Omron CX-Programmer project 新規ﾌﾟﾛｼﾞｪｸﾄ (CX-Programmer 9.70)

# PLC エレベータPLC: CJ2M CPU34
I/O table (CPU CJ2M-CPU34): rack 0 slot 0 CJ1W-ID231; rack 0 slot 1 CJ1W-ID231; rack 0 slot 2 CJ1W-OD231; rack 0 slot 11 CJ2M-EIP21

## Global symbols (name address type ; comment)
0.00 BOOL  ; 1F行PB(かご内)
0.01 BOOL  ; 2F行PB(かご内)
0.02 BOOL  ; 3F行PB(かご内)
0.03 BOOL  ; 開PB(かご内)
0.04 BOOL  ; 閉PB(かご内)
0.05 BOOL  ; 扉開LS(かご内)
0.06 BOOL  ; 扉閉LS(かご内)
1.00 BOOL  ; 呼びPB(1F)
1.01 BOOL  ; 呼びPB(2F)
1.02 BOOL  ; 呼びPB(3F)
1.03 BOOL  ; かご上限LS
1.04 BOOL  ; かご下限LS
1.05 BOOL  ; かご到着LS(1F)
1.06 BOOL  ; かご到着LS(2F)
1.07 BOOL  ; かご到着LS(3F)
1.08 BOOL  ; 扉開LS(1F)
1.09 BOOL  ; 扉閉LS(1F)
1.10 BOOL  ; 扉開LS(2F)
1.11 BOOL  ; 扉閉LS(2F)
1.12 BOOL  ; 扉開LS(3F)
1.13 BOOL  ; 扉閉LS(3F)
2.00 BOOL  ; 運転
2.01 BOOL  ; 調整
2.02 BOOL  ; 上昇PB
2.03 BOOL  ; 下降PB
2.04 BOOL  ; かご扉開PB
2.05 BOOL  ; かご扉閉PB
2.06 BOOL  ; 1F扉開PB
2.07 BOOL  ; 1F扉閉PB
2.08 BOOL  ; 2F扉開PB
2.09 BOOL  ; 2F扉閉PB
2.10 BOOL  ; 3F扉開PB
2.11 BOOL  ; 3F扉閉PB
4.00 BOOL  ; 下降
4.01 BOOL  ; 上昇
4.02 BOOL  ; 昇降ﾌﾞﾚｰｷ
4.03 BOOL  ; 扉開(かご)
4.04 BOOL  ; 扉閉(かご)
4.05 BOOL  ; 扉開(1F)
4.06 BOOL  ; 扉閉(1F)
4.07 BOOL  ; 扉開(2F)
4.08 BOOL  ; 扉閉(2F)
4.09 BOOL  ; 扉開(3F)
4.10 BOOL  ; 扉閉(3F)
5.00 BOOL  ; 行先1F表示(かご)
5.01 BOOL  ; 行先2F表示(かご)
5.02 BOOL  ; 行先3F表示(かご)
5.03 BOOL  ; 1F呼び表示
5.04 BOOL  ; 2F呼び表示
5.05 BOOL  ; 3F呼び表示
5.15 BOOL  ; 運転ﾓｰﾄﾞ
T0000 BOOL  ; 扉開遅延
T0001 BOOL  ; 扉閉待機
T0002 BOOL  ; 扉閉後動作完了信号遅延
W0.00 BOOL  ; 1F行き(かご内)
W0.01 BOOL  ; 2F行き(かご内)
W0.02 BOOL  ; 3F行き(かご内)
W0.03 BOOL  ; 下降信号
W0.04 BOOL  ; 上昇信号
W0.05 BOOL  ; 移動なし
W0.08 BOOL  ; 扉開(かご)
W0.09 BOOL  ; 扉閉(かご)
W10.00 BOOL  ; 停止中
W10.01 BOOL  ; 昇降開始
W10.02 BOOL  ; 下降
W10.03 BOOL  ; 上昇
W10.04 BOOL  ; 昇降停止
W10.05 BOOL  ; 1F呼び
W10.06 BOOL  ; 2F呼び
W10.07 BOOL  ; 3F呼び
W10.08 BOOL  ; 下降信号
W10.09 BOOL  ; 上昇信号
W10.10 BOOL  ; 1F呼び
W10.11 BOOL  ; 2F呼び
W10.12 BOOL  ; 3F呼び
W11.00 BOOL  ; 階到着扉開遅延
W11.02 BOOL  ; 扉閉待機
W11.03 BOOL  ; 扉閉完了
W11.06 BOOL  ; 扉開'(各階)
W11.07 BOOL  ; 扉閉(各階)

## Program 新規ﾌﾟﾛｸﾞﾗﾑ1 (cyclic task 0)

### Section かご内

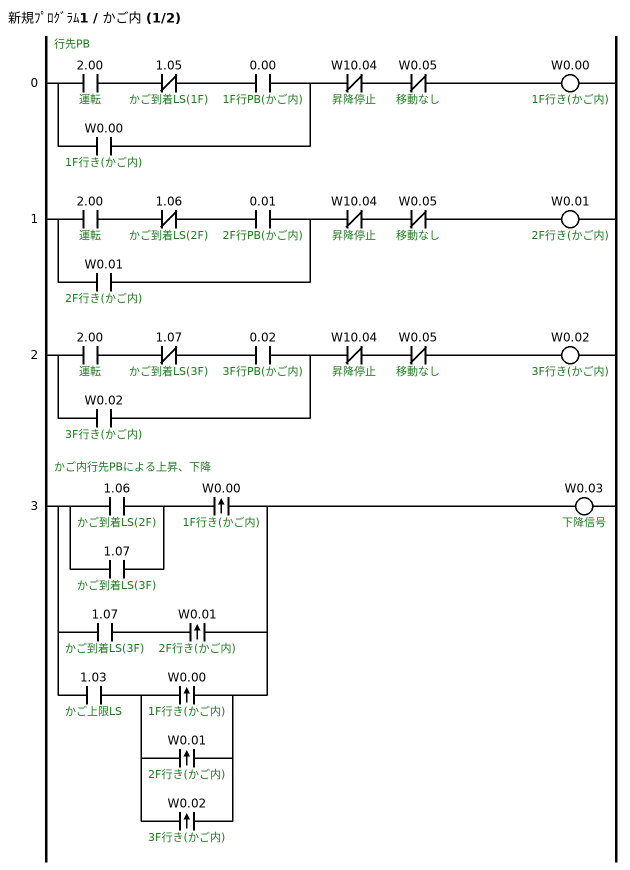
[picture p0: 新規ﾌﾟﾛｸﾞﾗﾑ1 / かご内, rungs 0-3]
; rung 0: 行先PB
LD 2.00  ; 運転
ANDNOT 1.05  ; かご到着LS(1F)
AND 0.00  ; 1F行PB(かご内)
OR W0.00  ; 1F行き(かご内)
ANDNOT W10.04  ; 昇降停止
ANDNOT W0.05  ; 移動なし
OUT W0.00  ; 1F行き(かご内)
; rung 1
LD 2.00  ; 運転
ANDNOT 1.06  ; かご到着LS(2F)
AND 0.01  ; 2F行PB(かご内)
OR W0.01  ; 2F行き(かご内)
ANDNOT W10.04  ; 昇降停止
ANDNOT W0.05  ; 移動なし
OUT W0.01  ; 2F行き(かご内)
; rung 2
LD 2.00  ; 運転
ANDNOT 1.07  ; かご到着LS(3F)
AND 0.02  ; 3F行PB(かご内)
OR W0.02  ; 3F行き(かご内)
ANDNOT W10.04  ; 昇降停止
ANDNOT W0.05  ; 移動なし
OUT W0.02  ; 3F行き(かご内)
; rung 3: かご内行先PBによる上昇、下降
LD 1.06  ; かご到着LS(2F)
OR 1.07  ; かご到着LS(3F)
@AND W0.00  ; 1F行き(かご内)
LD 1.07  ; かご到着LS(3F)
@AND W0.01  ; 2F行き(かご内)
ORLD
LD 1.03  ; かご上限LS
@LD W0.00  ; 1F行き(かご内)
@OR W0.01  ; 2F行き(かご内)
@OR W0.02  ; 3F行き(かご内)
ANDLD
ORLD
OUT W0.03  ; 下降信号

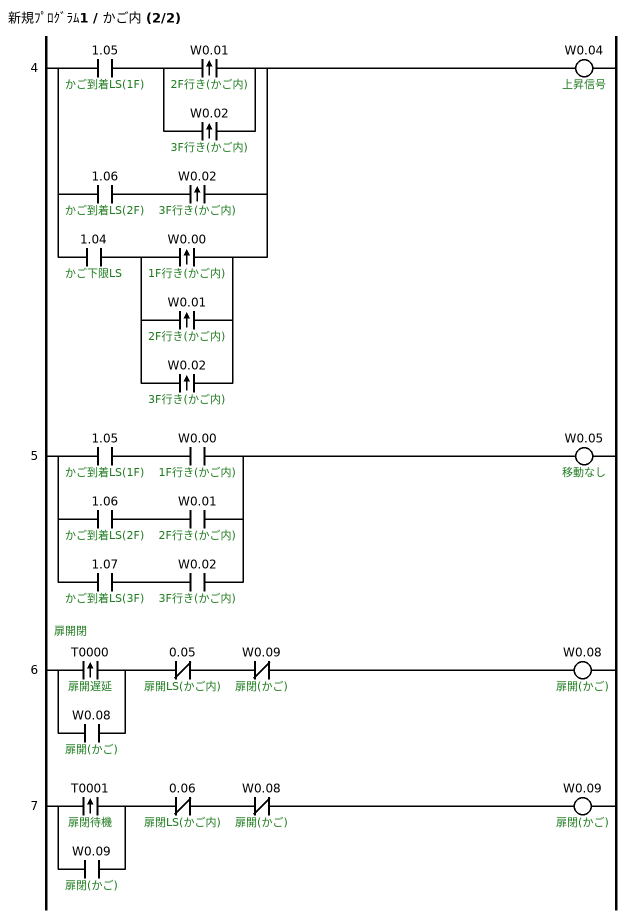
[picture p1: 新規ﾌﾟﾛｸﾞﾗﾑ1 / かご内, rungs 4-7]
; rung 4
LD 1.05  ; かご到着LS(1F)
@LD W0.01  ; 2F行き(かご内)
@OR W0.02  ; 3F行き(かご内)
ANDLD
LD 1.06  ; かご到着LS(2F)
@AND W0.02  ; 3F行き(かご内)
ORLD
LD 1.04  ; かご下限LS
@LD W0.00  ; 1F行き(かご内)
@OR W0.01  ; 2F行き(かご内)
@OR W0.02  ; 3F行き(かご内)
ANDLD
ORLD
OUT W0.04  ; 上昇信号
; rung 5
LD 1.05  ; かご到着LS(1F)
AND W0.00  ; 1F行き(かご内)
LD 1.06  ; かご到着LS(2F)
AND W0.01  ; 2F行き(かご内)
ORLD
LD 1.07  ; かご到着LS(3F)
AND W0.02  ; 3F行き(かご内)
ORLD
OUT W0.05  ; 移動なし
; rung 6: 扉開閉
@LD T0000  ; 扉開遅延
OR W0.08  ; 扉開(かご)
ANDNOT 0.05  ; 扉開LS(かご内)
ANDNOT W0.09  ; 扉閉(かご)
OUT W0.08  ; 扉開(かご)
; rung 7
@LD T0001  ; 扉閉待機
OR W0.09  ; 扉閉(かご)
ANDNOT 0.06  ; 扉閉LS(かご内)
ANDNOT W0.08  ; 扉開(かご)
OUT W0.09  ; 扉閉(かご)

### Section 地上

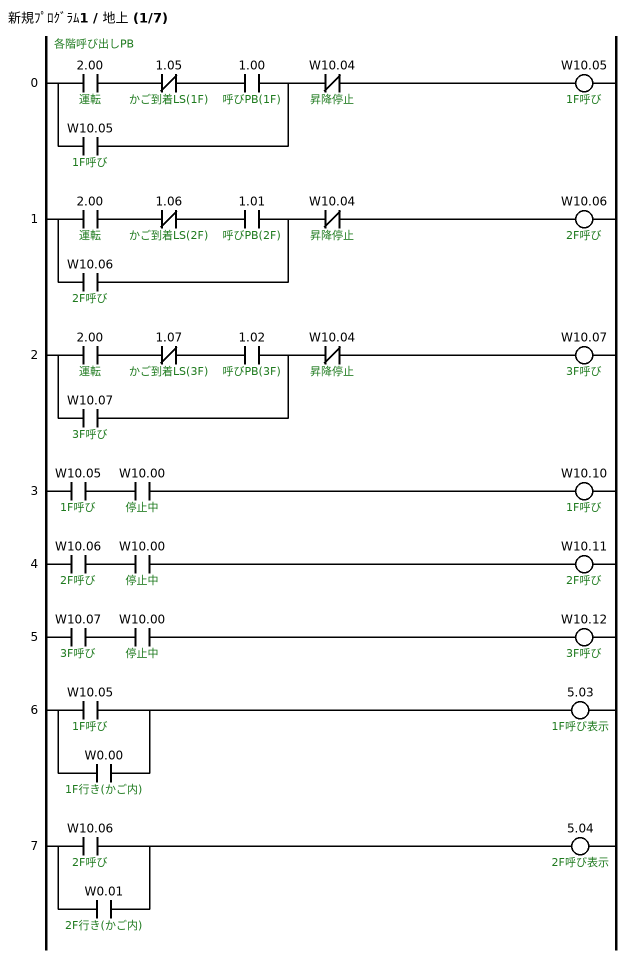
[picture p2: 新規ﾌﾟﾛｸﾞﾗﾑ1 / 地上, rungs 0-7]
; rung 0: 各階呼び出しPB
LD 2.00  ; 運転
ANDNOT 1.05  ; かご到着LS(1F)
AND 1.00  ; 呼びPB(1F)
OR W10.05  ; 1F呼び
ANDNOT W10.04  ; 昇降停止
OUT W10.05  ; 1F呼び
; rung 1
LD 2.00  ; 運転
ANDNOT 1.06  ; かご到着LS(2F)
AND 1.01  ; 呼びPB(2F)
OR W10.06  ; 2F呼び
ANDNOT W10.04  ; 昇降停止
OUT W10.06  ; 2F呼び
; rung 2
LD 2.00  ; 運転
ANDNOT 1.07  ; かご到着LS(3F)
AND 1.02  ; 呼びPB(3F)
OR W10.07  ; 3F呼び
ANDNOT W10.04  ; 昇降停止
OUT W10.07  ; 3F呼び
; rung 3
LD W10.05  ; 1F呼び
AND W10.00  ; 停止中
OUT W10.10  ; 1F呼び
; rung 4
LD W10.06  ; 2F呼び
AND W10.00  ; 停止中
OUT W10.11  ; 2F呼び
; rung 5
LD W10.07  ; 3F呼び
AND W10.00  ; 停止中
OUT W10.12  ; 3F呼び
; rung 6
LD W10.05  ; 1F呼び
OR W0.00  ; 1F行き(かご内)
OUT 5.03  ; 1F呼び表示
; rung 7
LD W10.06  ; 2F呼び
OR W0.01  ; 2F行き(かご内)
OUT 5.04  ; 2F呼び表示

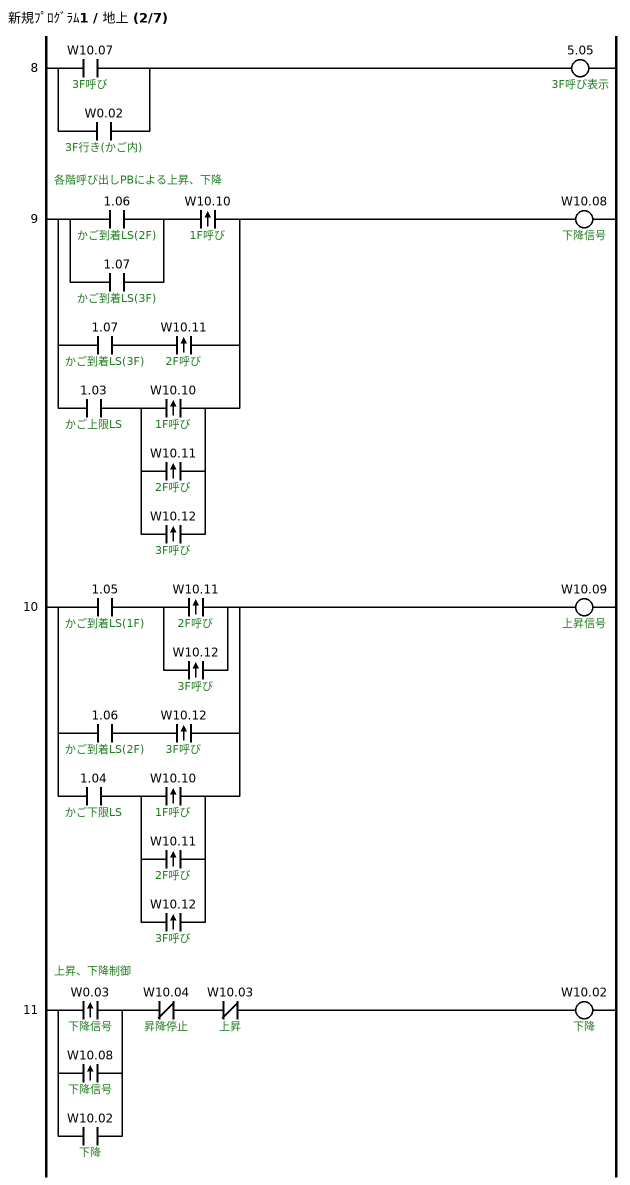
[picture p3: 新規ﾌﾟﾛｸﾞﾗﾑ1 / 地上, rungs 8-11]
; rung 8
LD W10.07  ; 3F呼び
OR W0.02  ; 3F行き(かご内)
OUT 5.05  ; 3F呼び表示
; rung 9: 各階呼び出しPBによる上昇、下降
LD 1.06  ; かご到着LS(2F)
OR 1.07  ; かご到着LS(3F)
@AND W10.10  ; 1F呼び
LD 1.07  ; かご到着LS(3F)
@AND W10.11  ; 2F呼び
ORLD
LD 1.03  ; かご上限LS
@LD W10.10  ; 1F呼び
@OR W10.11  ; 2F呼び
@OR W10.12  ; 3F呼び
ANDLD
ORLD
OUT W10.08  ; 下降信号
; rung 10
LD 1.05  ; かご到着LS(1F)
@LD W10.11  ; 2F呼び
@OR W10.12  ; 3F呼び
ANDLD
LD 1.06  ; かご到着LS(2F)
@AND W10.12  ; 3F呼び
ORLD
LD 1.04  ; かご下限LS
@LD W10.10  ; 1F呼び
@OR W10.11  ; 2F呼び
@OR W10.12  ; 3F呼び
ANDLD
ORLD
OUT W10.09  ; 上昇信号
; rung 11: 上昇、下降制御
@LD W0.03  ; 下降信号
@OR W10.08  ; 下降信号
OR W10.02  ; 下降
ANDNOT W10.04  ; 昇降停止
ANDNOT W10.03  ; 上昇
OUT W10.02  ; 下降

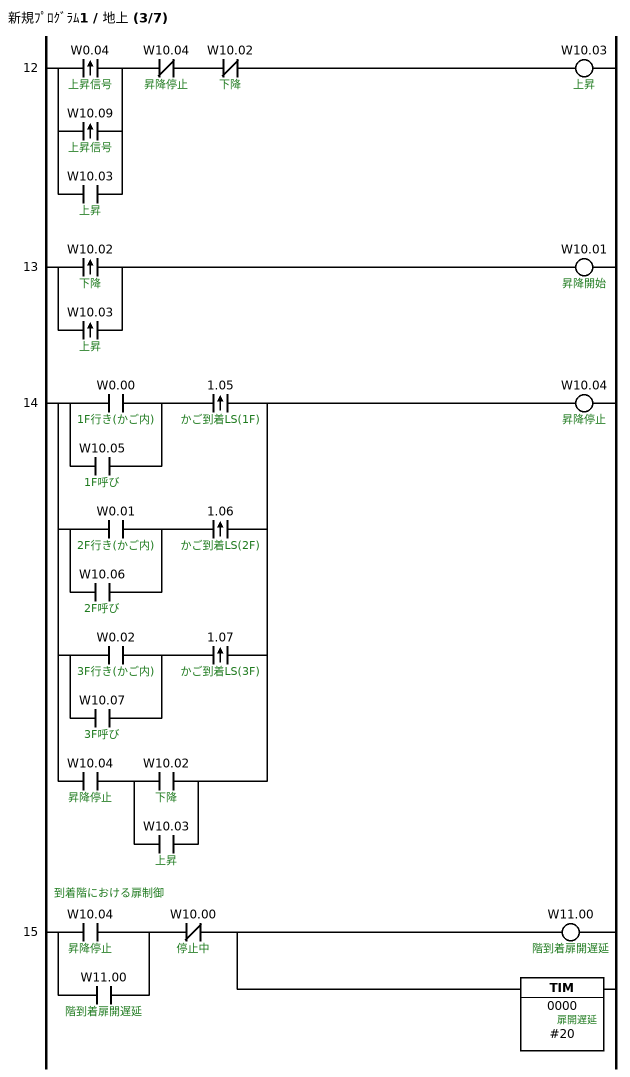
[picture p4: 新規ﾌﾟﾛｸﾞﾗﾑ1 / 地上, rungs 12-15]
; rung 12
@LD W0.04  ; 上昇信号
@OR W10.09  ; 上昇信号
OR W10.03  ; 上昇
ANDNOT W10.04  ; 昇降停止
ANDNOT W10.02  ; 下降
OUT W10.03  ; 上昇
; rung 13
@LD W10.02  ; 下降
@OR W10.03  ; 上昇
OUT W10.01  ; 昇降開始
; rung 14
LD W0.00  ; 1F行き(かご内)
OR W10.05  ; 1F呼び
@AND 1.05  ; かご到着LS(1F)
LD W0.01  ; 2F行き(かご内)
OR W10.06  ; 2F呼び
@AND 1.06  ; かご到着LS(2F)
ORLD
LD W0.02  ; 3F行き(かご内)
OR W10.07  ; 3F呼び
@AND 1.07  ; かご到着LS(3F)
ORLD
LD W10.04  ; 昇降停止
LD W10.02  ; 下降
OR W10.03  ; 上昇
ANDLD
ORLD
OUT W10.04  ; 昇降停止
; rung 15: 到着階における扉制御
LD W10.04  ; 昇降停止
OR W11.00  ; 階到着扉開遅延
ANDNOT W10.00  ; 停止中
OUT W11.00  ; 階到着扉開遅延
TIM 0000 #20  ; 扉開遅延

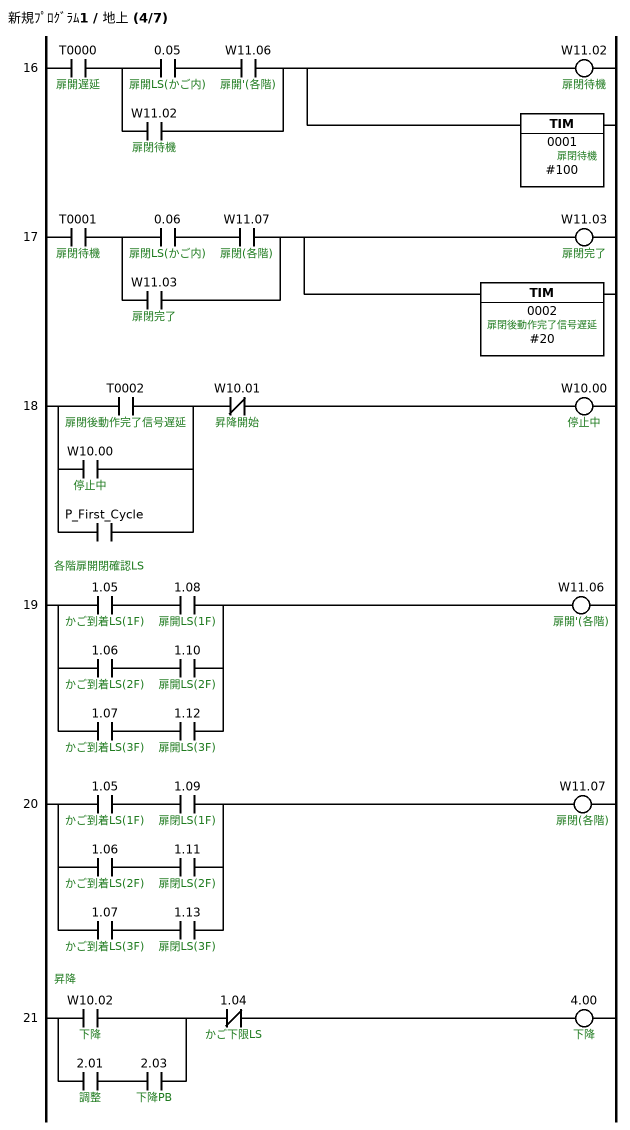
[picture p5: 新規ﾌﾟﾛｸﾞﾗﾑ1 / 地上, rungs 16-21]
; rung 16
LD T0000  ; 扉開遅延
LD 0.05  ; 扉開LS(かご内)
AND W11.06  ; 扉開'(各階)
OR W11.02  ; 扉閉待機
ANDLD
OUT W11.02  ; 扉閉待機
TIM 0001 #100  ; 扉閉待機
; rung 17
LD T0001  ; 扉閉待機
LD 0.06  ; 扉閉LS(かご内)
AND W11.07  ; 扉閉(各階)
OR W11.03  ; 扉閉完了
ANDLD
OUT W11.03  ; 扉閉完了
TIM 0002 #20  ; 扉閉後動作完了信号遅延
; rung 18
LD T0002  ; 扉閉後動作完了信号遅延
OR W10.00  ; 停止中
OR P_First_Cycle
ANDNOT W10.01  ; 昇降開始
OUT W10.00  ; 停止中
; rung 19: 各階扉開閉確認LS
LD 1.05  ; かご到着LS(1F)
AND 1.08  ; 扉開LS(1F)
LD 1.06  ; かご到着LS(2F)
AND 1.10  ; 扉開LS(2F)
ORLD
LD 1.07  ; かご到着LS(3F)
AND 1.12  ; 扉開LS(3F)
ORLD
OUT W11.06  ; 扉開'(各階)
; rung 20
LD 1.05  ; かご到着LS(1F)
AND 1.09  ; 扉閉LS(1F)
LD 1.06  ; かご到着LS(2F)
AND 1.11  ; 扉閉LS(2F)
ORLD
LD 1.07  ; かご到着LS(3F)
AND 1.13  ; 扉閉LS(3F)
ORLD
OUT W11.07  ; 扉閉(各階)
; rung 21: 昇降
LD W10.02  ; 下降
LD 2.01  ; 調整
AND 2.03  ; 下降PB
ORLD
ANDNOT 1.04  ; かご下限LS
OUT 4.00  ; 下降

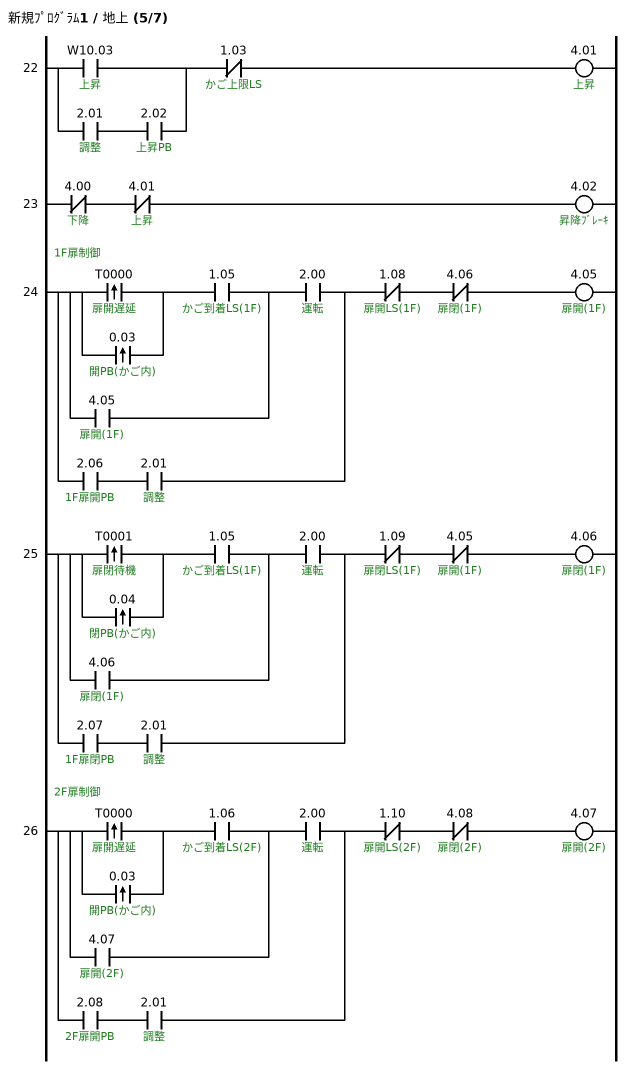
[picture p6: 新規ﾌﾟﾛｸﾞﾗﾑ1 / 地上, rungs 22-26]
; rung 22
LD W10.03  ; 上昇
LD 2.01  ; 調整
AND 2.02  ; 上昇PB
ORLD
ANDNOT 1.03  ; かご上限LS
OUT 4.01  ; 上昇
; rung 23
LDNOT 4.00  ; 下降
ANDNOT 4.01  ; 上昇
OUT 4.02  ; 昇降ﾌﾞﾚｰｷ
; rung 24: 1F扉制御
@LD T0000  ; 扉開遅延
@OR 0.03  ; 開PB(かご内)
AND 1.05  ; かご到着LS(1F)
OR 4.05  ; 扉開(1F)
AND 2.00  ; 運転
LD 2.06  ; 1F扉開PB
AND 2.01  ; 調整
ORLD
ANDNOT 1.08  ; 扉開LS(1F)
ANDNOT 4.06  ; 扉閉(1F)
OUT 4.05  ; 扉開(1F)
; rung 25
@LD T0001  ; 扉閉待機
@OR 0.04  ; 閉PB(かご内)
AND 1.05  ; かご到着LS(1F)
OR 4.06  ; 扉閉(1F)
AND 2.00  ; 運転
LD 2.07  ; 1F扉閉PB
AND 2.01  ; 調整
ORLD
ANDNOT 1.09  ; 扉閉LS(1F)
ANDNOT 4.05  ; 扉開(1F)
OUT 4.06  ; 扉閉(1F)
; rung 26: 2F扉制御
@LD T0000  ; 扉開遅延
@OR 0.03  ; 開PB(かご内)
AND 1.06  ; かご到着LS(2F)
OR 4.07  ; 扉開(2F)
AND 2.00  ; 運転
LD 2.08  ; 2F扉開PB
AND 2.01  ; 調整
ORLD
ANDNOT 1.10  ; 扉開LS(2F)
ANDNOT 4.08  ; 扉閉(2F)
OUT 4.07  ; 扉開(2F)

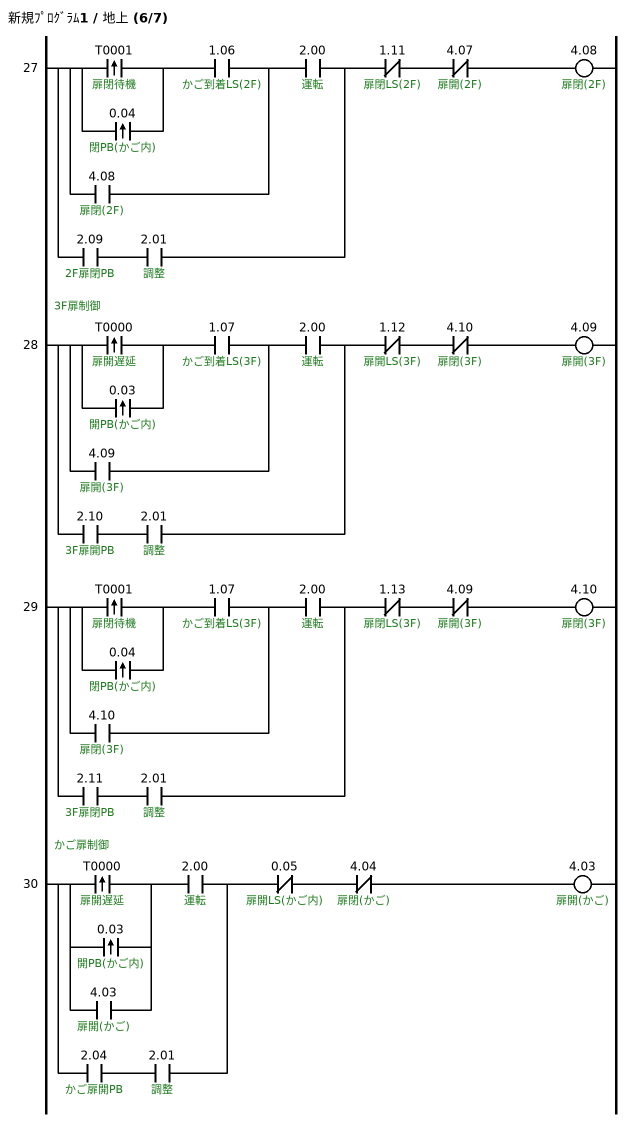
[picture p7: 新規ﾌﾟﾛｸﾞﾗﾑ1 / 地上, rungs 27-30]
; rung 27
@LD T0001  ; 扉閉待機
@OR 0.04  ; 閉PB(かご内)
AND 1.06  ; かご到着LS(2F)
OR 4.08  ; 扉閉(2F)
AND 2.00  ; 運転
LD 2.09  ; 2F扉閉PB
AND 2.01  ; 調整
ORLD
ANDNOT 1.11  ; 扉閉LS(2F)
ANDNOT 4.07  ; 扉開(2F)
OUT 4.08  ; 扉閉(2F)
; rung 28: 3F扉制御
@LD T0000  ; 扉開遅延
@OR 0.03  ; 開PB(かご内)
AND 1.07  ; かご到着LS(3F)
OR 4.09  ; 扉開(3F)
AND 2.00  ; 運転
LD 2.10  ; 3F扉開PB
AND 2.01  ; 調整
ORLD
ANDNOT 1.12  ; 扉開LS(3F)
ANDNOT 4.10  ; 扉閉(3F)
OUT 4.09  ; 扉開(3F)
; rung 29
@LD T0001  ; 扉閉待機
@OR 0.04  ; 閉PB(かご内)
AND 1.07  ; かご到着LS(3F)
OR 4.10  ; 扉閉(3F)
AND 2.00  ; 運転
LD 2.11  ; 3F扉閉PB
AND 2.01  ; 調整
ORLD
ANDNOT 1.13  ; 扉閉LS(3F)
ANDNOT 4.09  ; 扉開(3F)
OUT 4.10  ; 扉閉(3F)
; rung 30: かご扉制御
@LD T0000  ; 扉開遅延
@OR 0.03  ; 開PB(かご内)
OR 4.03  ; 扉開(かご)
AND 2.00  ; 運転
LD 2.04  ; かご扉開PB
AND 2.01  ; 調整
ORLD
ANDNOT 0.05  ; 扉開LS(かご内)
ANDNOT 4.04  ; 扉閉(かご)
OUT 4.03  ; 扉開(かご)

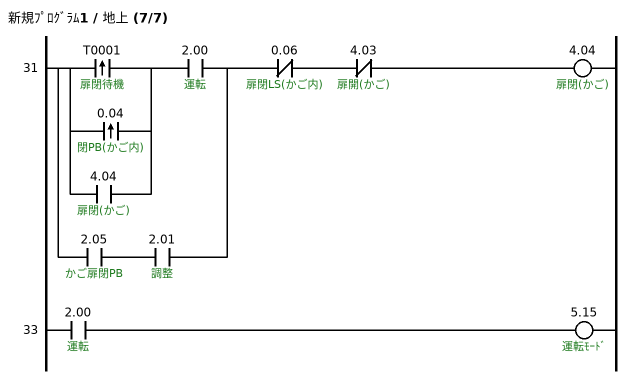
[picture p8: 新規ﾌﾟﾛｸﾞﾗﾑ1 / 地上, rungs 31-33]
; rung 31
@LD T0001  ; 扉閉待機
@OR 0.04  ; 閉PB(かご内)
OR 4.04  ; 扉閉(かご)
AND 2.00  ; 運転
LD 2.05  ; かご扉閉PB
AND 2.01  ; 調整
ORLD
ANDNOT 0.06  ; 扉閉LS(かご内)
ANDNOT 4.03  ; 扉開(かご)
OUT 4.04  ; 扉閉(かご)
; rung 33
LD 2.00  ; 運転
OUT 5.15  ; 運転ﾓｰﾄﾞ

### Section END
; rung 0
END(001)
